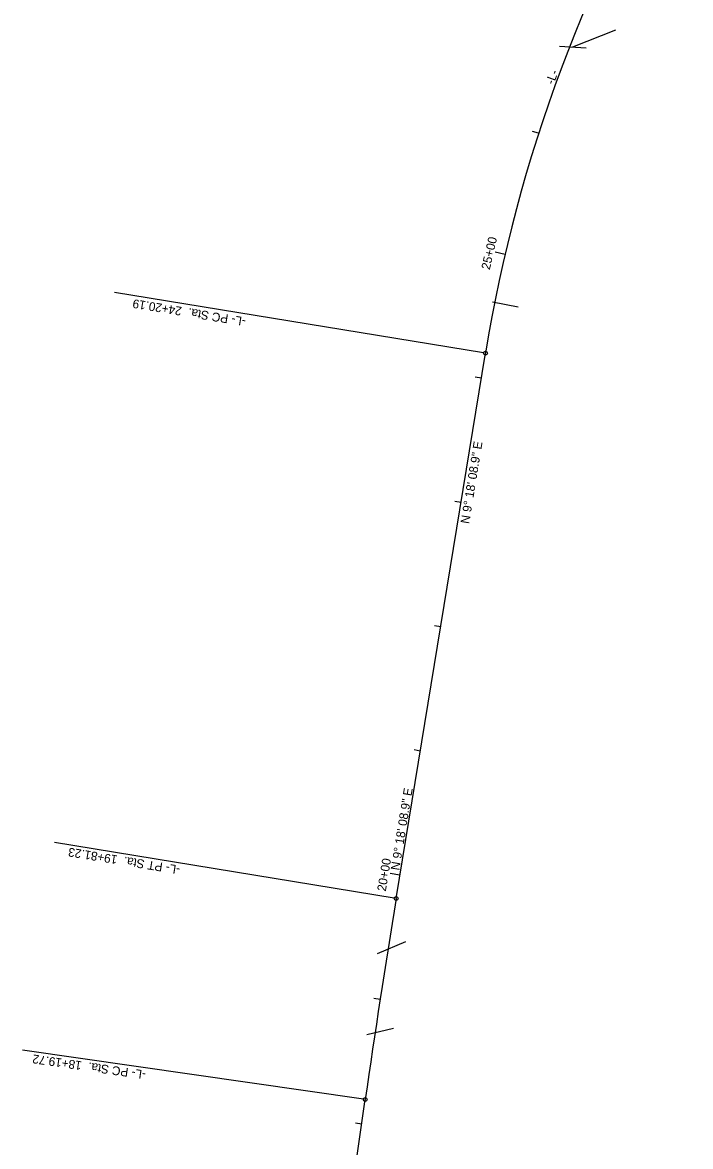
# Model space of a CAD drawing. Extents: x 1019959 to 1023888, y 635993 to 644996.
# Drawn here: x 1020316 to 1020846, y 636877 to 637770 of the extents above; entities that cross this region are included whole.
import ezdxf

# ---------------------------------------------------------------- set-up
doc = ezdxf.new("R2010")
doc.units = 0
for name, color, linetype in [('Cogo Default Point CELL', 7, 'Continuous'), ('COGO Default Point Elevation', 7, 'Continuous'), ('COGO Default Point Number', 7, 'Continuous'), ('Exist Roads EOT', 7, 'Continuous'), ('Exist Structure Minor Pipes CMP 24 Inch Cogo Number', 7, 'Continuous'), ('Exist Structure Minor Pipes CMP 24 Inch Cogo Point CELL', 7, 'Continuous'), ('Exist Utilities Power Pole CELL', 7, 'Continuous'), ('Exist Utilities Power Pole Cogo Number', 7, 'Continuous')]:
    doc.layers.add(name, color=color, linetype=linetype)

msp = doc.modelspace()

# ---------------------------------------------------------------- linework, layer by layer
at = {"layer": 'COGO Default Point Elevation'}
for p, q in [((1020725.7, 637681.56), (1020720.94, 637683.1)), ((1020680.21, 637487.03), (1020675.27, 637487.84)), ((1020664.04, 637388.34), (1020659.11, 637389.15)), ((1020647.88, 637289.66), (1020642.94, 637290.47)), ((1020631.71, 637190.97), (1020626.78, 637191.78)), ((1020599.78, 636993.54), (1020594.84, 636994.3)), ((1020585.17, 636894.61), (1020580.22, 636895.33))]:
    msp.add_line(p, q, dxfattribs=at)
at = {"layer": 'COGO Default Point Number'}
for p, q in [((1020698.98, 637585.23), (1020691.19, 637587.04)), ((1020615.55, 637092.29), (1020607.65, 637093.58))]:
    msp.add_line(p, q, dxfattribs=at)
at = {"layer": 'Exist Roads EOT'}
for p, q in [((1020681.99, 637507.2), (1020388.77, 637555.23)), ((1020611.03, 637074.01), (1020341.13, 637118.22)), ((1020586.49, 636914.35), (1020315.77, 636953.24))]:
    msp.add_line(p, q, dxfattribs=at)
for centre in [(1020683.47, 637506.96), (1020612.51, 637073.77), (1020587.98, 636914.14)]:
    msp.add_circle(centre, 1.5, dxfattribs=at)
at = {"layer": 'Exist Structure Minor Pipes CMP 24 Inch Cogo Number'}
for p, q in [((1020752.83, 637750.12), (1020786.96, 637763.8)), ((1020742.35, 637750.76), (1020763.31, 637749.47)), ((1020688.92, 637547.58), (1020709.42, 637543.83)), ((1020597.78, 637030.26), (1020620.16, 637039.75)), ((1020589.21, 636965.8), (1020610.39, 636970.77))]:
    msp.add_line(p, q, dxfattribs=at)
at = {"layer": 'Exist Structure Minor Pipes CMP 24 Inch Cogo Point CELL'}
for p, q in [((1020612.51, 637073.77), (1020683.47, 637506.96)), ((1020538.15, 636567.23), (1020587.98, 636914.14))]:
    msp.add_line(p, q, dxfattribs=at)
for centre, radius, start, end in [((1021867.69, 637312.98), 1200, 148.33757, 170.69753), ((1028704.67, 635748.27), 8200, 170.69753, 171.826024)]:
    msp.add_arc(centre, radius, start, end, dxfattribs=at)
at = {"layer": 'Exist Utilities Power Pole CELL'}
for p, q in [((1020612.51, 637073.77), (1020683.47, 637506.96)), ((1020538.15, 636567.23), (1020587.98, 636914.14))]:
    msp.add_line(p, q, dxfattribs=at)
for centre, radius, start, end in [((1021867.69, 637312.98), 1200, 148.33757, 170.69753), ((1028704.67, 635748.27), 8200, 170.69753, 171.826024)]:
    msp.add_arc(centre, radius, start, end, dxfattribs=at)

# ---------------------------------------------------------------- texts
at = {"layer": 'Cogo Default Point CELL'}
for s, rotation, p in [('25+00', 76.88708, (1020686.84, 637572.78)), ('20+00', 80.69753, (1020604.28, 637079.17))]:
    msp.add_text(s, height=7, rotation=rotation, dxfattribs=at).set_placement(p)
at = {"layer": 'Exist Roads EOT'}
for s, rotation, p in [('-L- PC Sta.  24+20.19', 170.69753, (1020493.52, 637535.2)), ('-L- PT Sta.  19+81.23', 170.69753, (1020441.36, 637099.77)), ('-L- PC Sta.  18+19.72', 171.82602, (1020414.17, 636937.08))]:
    msp.add_text(s, height=7, rotation=rotation, dxfattribs=at).set_placement(p)
at = {"layer": 'Exist Utilities Power Pole Cogo Number'}
for s, rotation, p in [('-L-', 69.72511, (1020737.56, 637719.75)), ('N 9%%d 18\' 08.9" E', 80.69753, (1020670.49, 637371.06)), ('N 9%%d 18\' 08.9" E', 80.69753, (1020615.02, 637095.81))]:
    msp.add_text(s, height=7, rotation=rotation, dxfattribs=at).set_placement(p)

doc.saveas('drawing.dxf')
